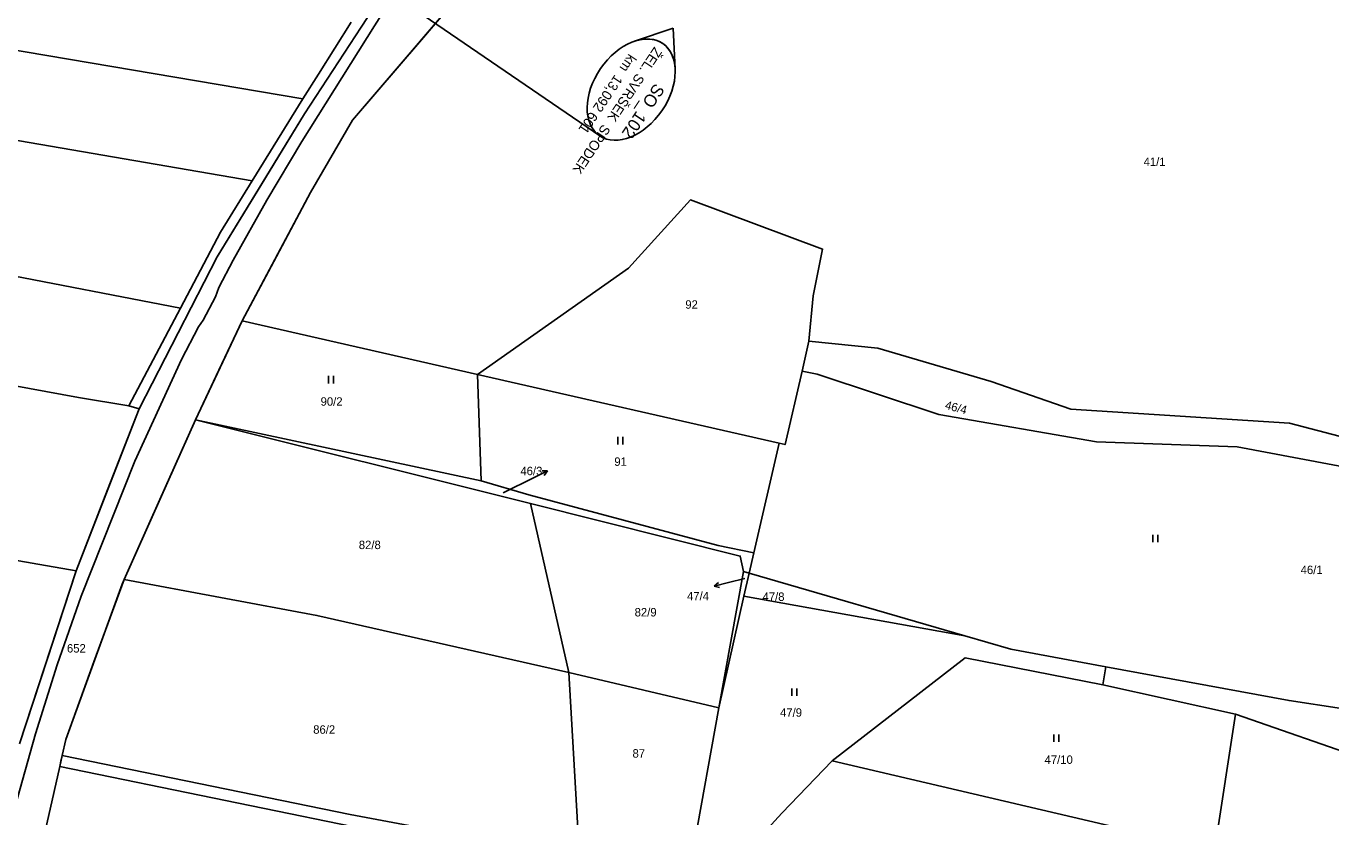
# Model space of a CAD drawing. Extents: x -746176 to -739709, y -1128407 to -1124482.
# Drawn here: x -743303 to -743040.3, y -1127345.9 to -1127186.5 of the extents above; entities that cross this region are included whole.
import ezdxf

# ---------------------------------------------------------------- set-up
doc = ezdxf.new("R2010")
doc.units = 0
for name, color, linetype in [('Vrstva 18', 7, 'Continuous'), ('Vrstva 32', 7, 'Continuous'), ('Vrstva 33', 7, 'Continuous'), ('Vrstva 34', 7, 'Continuous'), ('Vrstva 35', 7, 'Continuous'), ('Vrstva 42', 7, 'Continuous'), ('Vrstva 43', 7, 'Continuous'), ('Vrstva 44', 7, 'Continuous'), ('Vrstva 5', 7, 'Continuous')]:
    doc.layers.add(name, color=color, linetype=linetype)

msp = doc.modelspace()

# ---------------------------------------------------------------- linework, layer by layer
at = {"layer": 'Vrstva 18'}
msp.add_lwpolyline([(-743072.49, -1126932.75), (-743098.65, -1126974.15), (-743125.94, -1127017.38), (-743152.6, -1127059.61), (-743175.02, -1127095.12), (-743199.16, -1127133.35), (-743215.97, -1127159.94), (-743232.82, -1127186.51), (-743247.46, -1127209.81), (-743254.52, -1127221.64), (-743261.3, -1127233.69), (-743264.16, -1127239.2), (-743264.86, -1127241.11), (-743267.34, -1127245.82), (-743268.29, -1127247.16), (-743271.71, -1127253.75), (-743281.12, -1127274.2), (-743291.92, -1127301.42), (-743296.72, -1127315.22), (-743301.12, -1127329.13), (-743306.79, -1127349.51)], dxfattribs=at)
at = {"layer": 'Vrstva 33'}
for p, q in [((-743257.45, -1127217.75), (-743247.25, -1127201.23)), ((-743282.34, -1127263.07), (-743271.94, -1127243.4)), ((-743259.48, -1127245.93), (-743268.91, -1127265.85)), ((-743259.48, -1127245.93), (-743212.13, -1127256.74)), ((-743145.38, -1127250.03), (-743146.77, -1127256.08)), ((-743211.37, -1127278.18), (-743212.13, -1127256.74)), ((-743151.39, -1127270.6), (-743212.13, -1127256.74)), ((-743292.92, -1127296.34), (-743280.26, -1127263.68)), ((-743280.26, -1127263.68), (-743282.34, -1127263.07)), ((-743268.91, -1127265.85), (-743283.26, -1127298.02)), ((-743211.37, -1127278.18), (-743268.91, -1127265.85)), ((-743268.91, -1127265.85), (-743201.41, -1127282.77)), ((-743151.39, -1127270.6), (-743156.49, -1127292.65)), ((-743193.71, -1127316.81), (-743201.41, -1127282.77)), ((-743156.49, -1127292.65), (-743157.42, -1127296.78)), ((-743158.58, -1127296.44), (-743163.52, -1127323.93)), ((-743158.58, -1127296.44), (-743157.42, -1127296.78)), ((-743158.46, -1127301.41), (-743157.42, -1127296.78)), ((-743157.42, -1127296.78), (-743113.98, -1127309.38)), ((-743163.52, -1127323.93), (-743158.46, -1127301.41)), ((-743158.46, -1127301.41), (-743113.98, -1127309.38)), ((-743193.71, -1127316.81), (-743163.52, -1127323.93)), ((-743085.6, -1127315.62), (-743086.21, -1127319.28)), ((-743086.21, -1127319.28), (-743059.46, -1127325.17)), ((-743163.52, -1127323.93), (-743169.65, -1127358.07)), ((-743063.68, -1127352.59), (-743059.46, -1127325.17)), ((-743295.73, -1127333.53), (-743296.23, -1127335.74)), ((-743063.68, -1127352.59), (-743140.7, -1127334.62))]:
    msp.add_line(p, q, dxfattribs=at)
for points in [[(-743280.26, -1127263.68), (-743264.54, -1127233.06), (-743246.95, -1127204.21), (-743235.54, -1127186.77), (-743205.03, -1127140.21), (-743183.34, -1127102.57)], [(-743247.25, -1127201.23), (-743341.69, -1127185.22), (-743377.67, -1127178.61), (-743471.09, -1127163.04), (-743495.31, -1127157.9), (-743521.74, -1127151.29), (-743534.96, -1127147.61), (-743558.76, -1127136.98)], [(-743195.51, -1127141.13), (-743196.63, -1127142.85), (-743203.92, -1127154.43), (-743215.95, -1127172.74), (-743210.36, -1127174.02), (-743237.28, -1127205.49), (-743245.75, -1127220.06), (-743259.48, -1127245.93)], [(-743247.25, -1127201.23), (-743244.15, -1127196.22), (-743237.55, -1127185.73)], [(-743282.34, -1127263.07), (-743292.44, -1127261.41), (-743340.01, -1127252.63), (-743486.97, -1127227.24), (-743525.49, -1127217.7), (-743548.02, -1127210.66), (-743568.07, -1127202.32), (-743593.92, -1127190.2)], [(-743257.45, -1127217.75), (-743319.64, -1127207.06), (-743397.19, -1127192.74)], [(-743292.92, -1127296.34), (-743359.24, -1127284.78), (-743489.36, -1127263.15), (-743542.82, -1127249.21), (-743559.61, -1127242.69), (-743582.27, -1127231.48), (-743610.18, -1127214.83)], [(-743271.94, -1127243.4), (-743263.84, -1127228.1), (-743257.45, -1127217.75)], [(-743271.94, -1127243.4), (-743309.52, -1127236.1), (-743402, -1127219.97)], [(-743212.13, -1127256.74), (-743181.72, -1127235.32), (-743169.21, -1127221.57), (-743142.61, -1127231.48), (-743144.55, -1127240.89), (-743145.38, -1127250.03)], [(-743145.38, -1127250.03), (-743131.52, -1127251.43), (-743108.65, -1127258.13), (-743092.65, -1127263.72), (-743048.6, -1127266.53), (-743009.87, -1127276.7), (-742990.61, -1127278.9), (-742978.14, -1127278.38)], [(-743146.77, -1127256.08), (-743150.16, -1127270.88), (-743151.39, -1127270.6)], [(-742969.89, -1127289.73), (-742969.99, -1127290.93), (-743008.17, -1127280.91), (-743059.17, -1127271.35), (-743087.47, -1127270.29), (-743119.25, -1127264.8), (-743143.75, -1127256.66), (-743146.77, -1127256.08)], [(-743156.49, -1127292.65), (-743163.66, -1127291.17), (-743201.78, -1127281.02), (-743211.37, -1127278.18)], [(-743201.41, -1127282.77), (-743159.21, -1127293.35), (-743158.58, -1127296.44)], [(-743304.3, -1127331.19), (-743293.07, -1127296.72), (-743292.92, -1127296.34)], [(-743283.26, -1127298.02), (-743283.68, -1127298.96), (-743294.99, -1127330.28), (-743295.73, -1127333.53)], [(-743283.26, -1127298.02), (-743244.44, -1127305.3), (-743193.71, -1127316.81)], [(-743113.98, -1127309.38), (-743104.71, -1127312.07), (-743085.6, -1127315.62)], [(-743140.7, -1127334.62), (-743113.92, -1127313.85), (-743086.21, -1127319.28)], [(-743295.73, -1127333.53), (-743237.76, -1127345.4), (-743191.59, -1127354.07), (-743193.71, -1127316.81)], [(-743085.6, -1127315.62), (-743048.7, -1127322.46), (-743017.08, -1127327.24), (-743009.69, -1127326.1)], [(-743059.46, -1127325.17), (-743032.86, -1127334.46), (-743014.16, -1127339.69)], [(-743296.23, -1127335.74), (-743299.98, -1127352.31), (-743302.98, -1127364.26)], [(-743170.53, -1127362.98), (-743196.16, -1127356.25), (-743296.23, -1127335.74)], [(-743140.7, -1127334.62), (-743150.85, -1127345.11), (-743161.95, -1127357.36)]]:
    msp.add_lwpolyline(points, dxfattribs=at)
at = {"layer": 'Vrstva 34'}
msp.add_line((-743187.51, -1127208.64), (-743227.07, -1127181.59), dxfattribs=at)
at = {"layer": 'Vrstva 35'}
for p, q in [((-743172.69, -1127186.98), (-743180.52, -1127189.6)), ((-743172.69, -1127186.98), (-743180.52, -1127189.6)), ((-743172.3, -1127195.22), (-743172.69, -1127186.98)), ((-743172.3, -1127195.22), (-743172.69, -1127186.98))]:
    msp.add_line(p, q, dxfattribs=at)
msp.add_ellipse((-743181.16, -1127199.36), major_axis=(-6.35, -9.29), ratio=0.666667, dxfattribs=at)
msp.add_ellipse((-743181.16, -1127199.36), major_axis=(6.35, 9.29), ratio=0.666473, start_param=5.557317, end_param=7.009053, dxfattribs=at)
at = {"layer": 'Vrstva 43'}
for p, q in [((-743206.97, -1127280.56), (-743200.69, -1127277.5)), ((-743200.69, -1127277.5), (-743197.99, -1127276.18)), ((-743197.99, -1127276.18), (-743199.11, -1127276.17)), ((-743197.99, -1127276.18), (-743198.67, -1127277.07)), ((-743161.54, -1127298.69), (-743164.45, -1127299.42)), ((-743164.45, -1127299.42), (-743163.6, -1127298.69)), ((-743164.45, -1127299.42), (-743163.36, -1127299.66)), ((-743158.26, -1127297.86), (-743161.54, -1127298.69))]:
    msp.add_line(p, q, dxfattribs=at)
at = {"layer": 'Vrstva 44'}
for p, q in [((-743242.13, -1127258.55), (-743242.13, -1127257.05)), ((-743241.13, -1127258.55), (-743241.13, -1127257.05)), ((-743183.86, -1127270.84), (-743183.86, -1127269.34)), ((-743182.86, -1127270.84), (-743182.86, -1127269.34)), ((-743076.14, -1127290.53), (-743076.14, -1127289.03)), ((-743075.14, -1127290.53), (-743075.14, -1127289.03)), ((-743148.81, -1127321.49), (-743148.81, -1127319.99)), ((-743147.81, -1127321.49), (-743147.81, -1127319.99)), ((-743096.07, -1127330.79), (-743096.07, -1127329.29)), ((-743095.07, -1127330.79), (-743095.07, -1127329.29))]:
    msp.add_line(p, q, dxfattribs=at)
at = {"layer": 'Vrstva 5'}
for points in [[(-743304.3, -1127331.19), (-743298.69, -1127313.96), (-743293.07, -1127296.72), (-743292.92, -1127296.34), (-743286.59, -1127280.01), (-743280.26, -1127263.68), (-743264.54, -1127233.06), (-743255.75, -1127218.64), (-743246.95, -1127204.21), (-743235.54, -1127186.77), (-743220.29, -1127163.49)], [(-743210.36, -1127174.02), (-743223.82, -1127189.76), (-743237.28, -1127205.49), (-743245.75, -1127220.06), (-743252.61, -1127233), (-743259.48, -1127245.93), (-743264.2, -1127255.89), (-743268.91, -1127265.85), (-743276.08, -1127281.94), (-743283.26, -1127298.02), (-743289.33, -1127314.62), (-743294.99, -1127330.28), (-743295.73, -1127333.53), (-743295.98, -1127334.64), (-743296.23, -1127335.74), (-743299.98, -1127352.31)]]:
    msp.add_lwpolyline(points, dxfattribs=at)

# ---------------------------------------------------------------- texts
at = {"layer": 'Vrstva 32'}
for s, height, p in [('ŽEL. SVRŠEK  SPODEK', 2, (-743176.49, -1127190.61)), ('km  13,092 601', 2, (-743181.63, -1127192)), ('SO_102', 2.5, (-743176.36, -1127197.92))]:
    msp.add_text(s, height=height, rotation=236.3041, dxfattribs=at).set_placement(p)
at = {"layer": 'Vrstva 42'}
for s, p in [('41/1', (-743077.99, -1127214.74)), ('92', (-743170.27, -1127243.5)), ('90/2', (-743243.7, -1127263.04)), ('91', (-743184.56, -1127275.15)), ('46/3', (-743203.47, -1127277.04)), ('82/8', (-743236.01, -1127291.93)), ('46/1', (-743046.37, -1127296.96)), ('47/4', (-743169.93, -1127302.26)), ('47/8', (-743154.72, -1127302.37)), ('82/9', (-743180.47, -1127305.5)), ('652', (-743294.77, -1127312.77)), ('47/9', (-743151.19, -1127325.7)), ('86/2', (-743245.19, -1127329.13)), ('87', (-743180.9, -1127333.94)), ('47/10', (-743097.93, -1127335.2))]:
    msp.add_text(s, height=1.7, dxfattribs=at).set_placement(p)
msp.add_text('46/4', height=1.7, rotation=345, dxfattribs=at).set_placement((-743118.1, -1127263.64))

doc.saveas('drawing.dxf')
